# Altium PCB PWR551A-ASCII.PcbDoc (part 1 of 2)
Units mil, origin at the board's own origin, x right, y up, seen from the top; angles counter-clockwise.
Board outline 7100 x 3800 mil, 2 copper layers (Top Layer, Bottom Layer), stack 62 mil thick; 141 components, 57 nets, 323 pads, 168 vias.
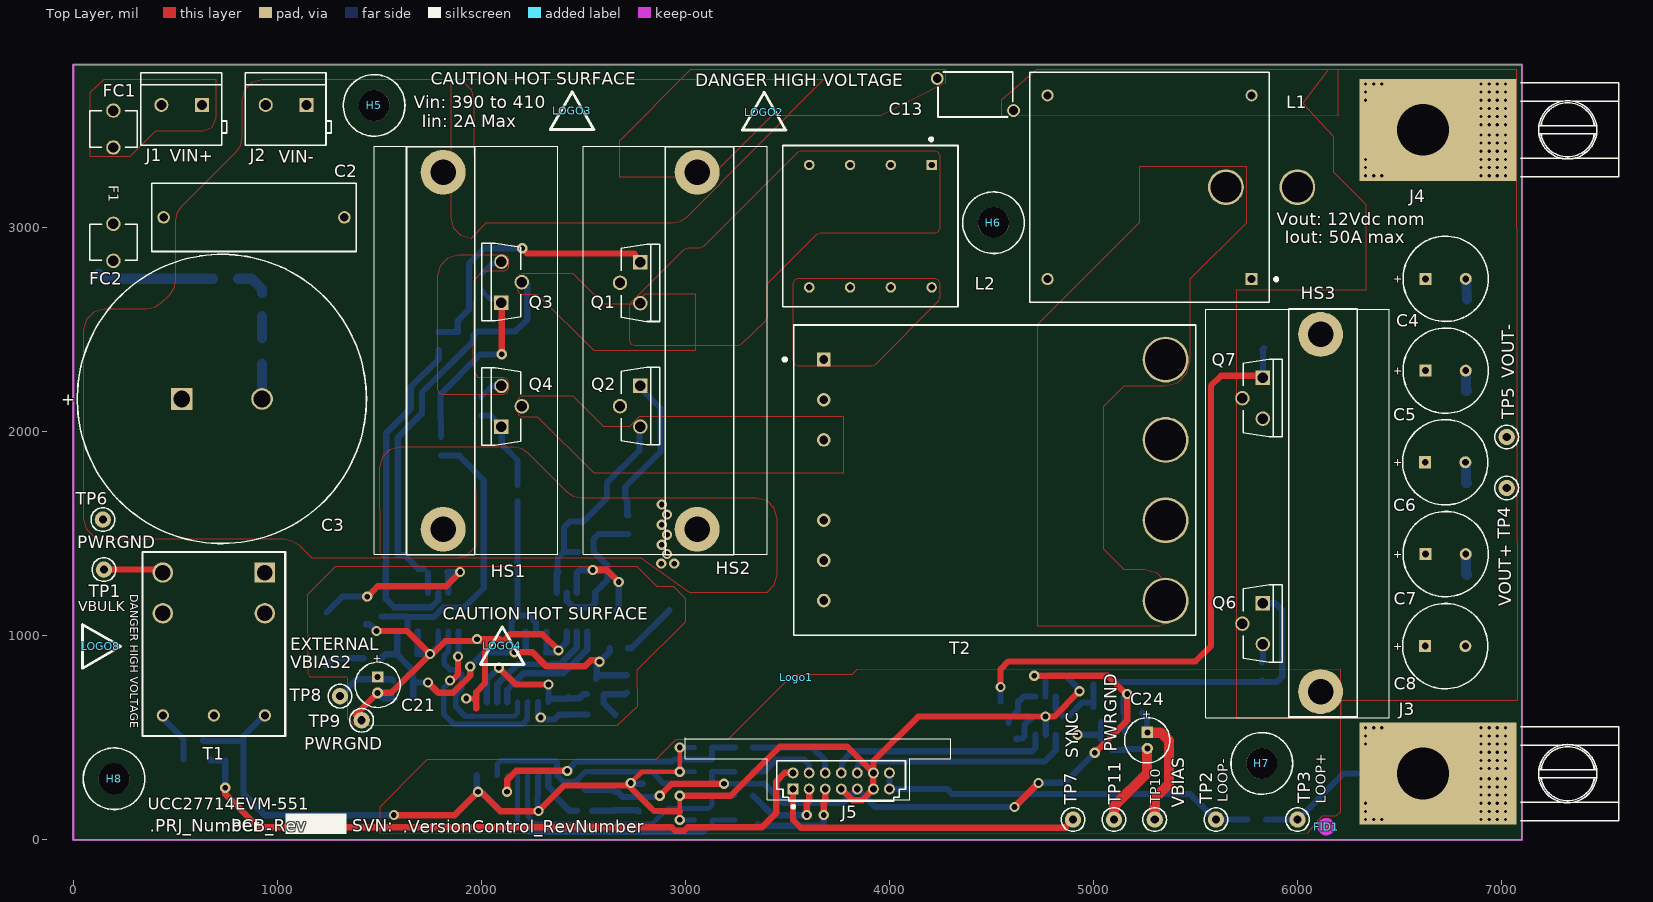
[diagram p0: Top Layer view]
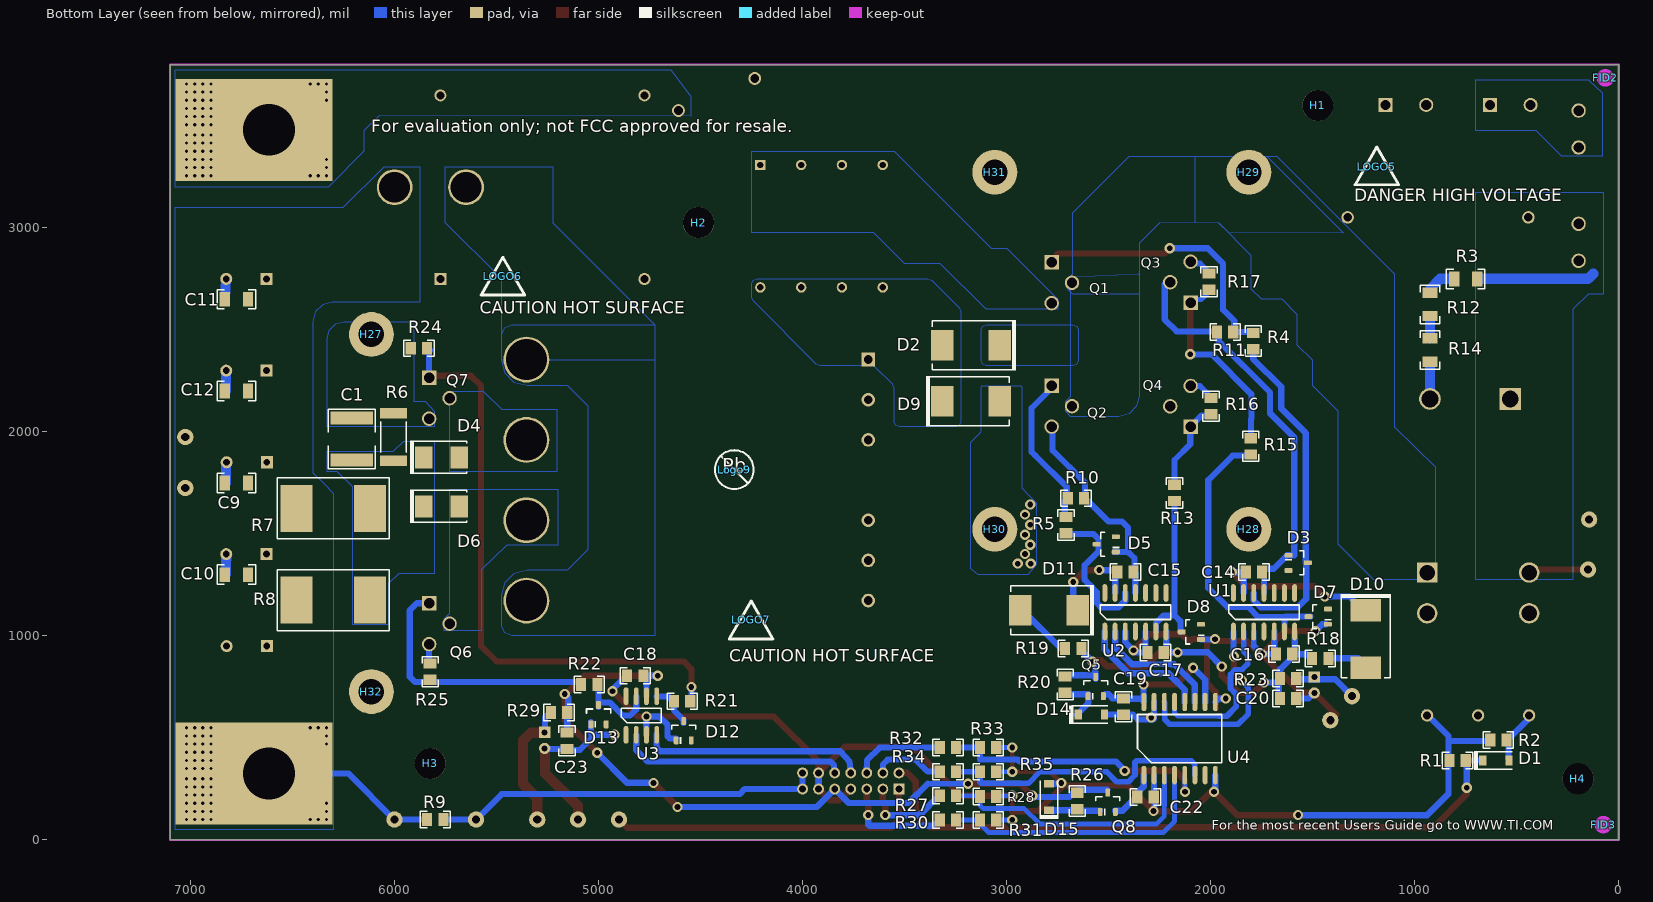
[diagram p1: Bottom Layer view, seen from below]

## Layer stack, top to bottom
Top Layer: signal copper 1.4
Dielectric: core 59.2, FR-4, Dk 4.8
Bottom Layer: signal copper 1.4

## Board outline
0,0 0,3800 7100,3800 7100,0

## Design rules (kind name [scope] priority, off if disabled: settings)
AcuteAngle [All] p0: scope1count=1 scope1_0_kind=Board scope1_0_value=Board scope2count=1 scope2_0_kind=Board scope2_0_value=Board commentlength=0 minimum=4.50000000000000E+0001
AcuteAngle [All] p1: minimum=4.50000000000000E+0001 checktracksonly=TRUE
AssemblyTestPointUsage [All] p0: scope1count=1 scope1_0_kind=Board scope1_0_value=Board scope2count=1 scope2_0_kind=Board scope2_0_value=Board commentlength=0
AssemblyTestPointUsage [All] p1: valid=2
AssemblyTestpoint [All] p0: scope1count=1 scope1_0_kind=Board scope1_0_value=Board scope2count=1 scope2_0_kind=Board scope2_0_value=Board commentlength=0
Clearance Clearance_ALL [All] p0: scope1count=1 scope1_0_kind=Board scope1_0_value=Board scope2count=1 scope2_0_kind=Board scope2_0_value=Board commentlength=0 gap=12
Clearance Clearance_BoardEdge [All] p0 off: scope1count=1 scope1_0_kind=Board scope1_0_value=Board scope2count=1 scope2_0_kind=Board scope2_0_value=Board commentlength=48 gap=19.68 // Protel DXP Scope 2 Expression Was: IsKeepout
Clearance Clearance_BoardEdge_Poly [All] p0 off: scope1count=1 scope1_0_kind=Board scope1_0_value=Board scope2count=1 scope2_0_kind=Board scope2_0_value=Board commentlength=48 gap=19.68 // Protel DXP Scope 2 Expression Was: IsKeepOut
Clearance Clearance_BoardEdge_MountingHoles [All] p0 off: scope1count=1 scope1_0_kind=Board scope1_0_value=Board scope2count=1 scope2_0_kind=Board scope2_0_value=Board commentlength=48 gap=12 // Protel DXP Scope 2 Expression Was: IsKeepOut
Clearance Clearance_Poly [All] p0 off: scope1count=1 scope1_0_kind=Board scope1_0_value=Board scope2count=1 scope2_0_kind=Board scope2_0_value=Board commentlength=48 gap=12 // Protel DXP Scope 1 Expression Was: InPolygon
Clearance ClearanceSW [All] p0 off: scope1count=1 scope1_0_kind=NetClass scope1_0_value=SW scope2count=1 scope2_0_kind=Board scope2_0_value=Board commentlength=75 gap=39.37 // Protel DXP Scope 2 Expression Was: InNetClass('HV') OR InNetClass('LV')
Clearance ClearanceHV [All] p0: scope1count=1 scope1_0_kind=NetClass scope1_0_value=HV scope2count=1 scope2_0_kind=NetClass scope2_0_value="All Nets" commentlength=0 gap=39.37
Clearance Clearance-PRI-SEC [All] p0 off: scope1count=1 scope1_0_kind=NetClass scope1_0_value=SEC scope2count=1 scope2_0_kind=Board scope2_0_value=Board commentlength=95 gap=314.96 // Protel DXP Scope 2 Expression Was: InNetClass('HV') OR InNetClass('SW') OR InNetClass('LV')
Clearance Clearance-PRI-SEC [InNetClass('SEC') vs InNetClass('HV') OR InNetClass('SW') OR InNetClass('LV')] p1: gap=314.96
Clearance ClearanceHV [InNetClass('HV') vs InNetClass('All Nets')] p2: gap=39.37
Clearance ClearanceSW [InNetClass('SW') vs InNetClass('HV') OR InNetClass('LV')] p3: gap=39.37
Clearance Clearance_Poly [InPolygon] p4: gap=12
Clearance Clearance_BoardEdge_MountingHoles [OnCopper and InComponentClass('Mounting Holes') vs IsKeepOut] p5: gap=12
Clearance Clearance_BoardEdge_Poly [OnCopper and InPoly vs IsKeepOut] p6: gap=19.68
Clearance Clearance_BoardEdge [OnCopper and Not InComponentClass('Logo') and not InComponentClass('FiducialMark') and not InRegion(1000,500,4000,800) and Not IsKeepout vs IsKeepout] p7: gap=19.68
Clearance Clearance_ALL [All] p8: gap=12
ComponentClearance [All] p0: scope1count=1 scope1_0_kind=Board scope1_0_value=Board scope2count=1 scope2_0_kind=Board scope2_0_value=Board commentlength=0 gap=0 collisioncheckmode=3
ComponentClearance ComponentClearance_THtoTH [All] p0 off: scope1count=1 scope1_0_kind=Board scope1_0_value=Board scope2count=1 scope2_0_kind=Board scope2_0_value=Board commentlength=54 gap=7.87 collisioncheckmode=3 // Protel DXP Scope 2 Expression Was: IsThruComponent
ComponentClearance ComponentClearance_THtoSMT [All] p0 off: scope1count=1 scope1_0_kind=Board scope1_0_value=Board scope2count=1 scope2_0_kind=Board scope2_0_value=Board commentlength=53 gap=7.87 collisioncheckmode=3 // Protel DXP Scope 2 Expression Was: IsSMTComponent
ComponentClearance ComponentClearance_SmallPassives [All] p0 off: scope1count=1 scope1_0_kind=Board scope1_0_value=Board scope2count=1 scope2_0_kind=Board scope2_0_value=Board commentlength=508 gap=7.87 collisioncheckmode=3 // Protel DXP Scope 2 Expression Was: HasFootprint('0201*') or HasFootprint('0402*') or HasFootprint('0508') or HasFootprint('0603*') or HasFootprint('0612') or HasFootprint('0805*') or HasFootprint('0815*') or HasFootprint('0830*') or HasFootprint('1206*') or HasFootprint('1210*') or HasFootprint('1808*') or HasFootprint('1812*') or HasFootprint('1825*') or HasFootprint('2010*') or HasFootprint('2220*') or HasFootprint('2225*') or HasFootprint('2512*') or HasFootprint('2728*') or HasFootprint('3518*')
ComponentClearance ComponentClearance_MountingHoles [All] p0: scope1count=1 scope1_0_kind=ComponentClass scope1_0_value="Mounting Holes" scope2count=1 scope2_0_kind=Board scope2_0_value=Board commentlength=0 gap=19.68 collisioncheckmode=3
ComponentClearance ComponentClearance_ScrewToNut [All] p0 off: scope1count=1 scope1_0_kind=Board scope1_0_value=Board scope2count=1 scope2_0_kind=Board scope2_0_value=Board commentlength=71 gap=0 collisioncheckmode=3 // Protel DXP Scope 2 Expression Was: (HasFootprint('Keystone_1902C'))
ComponentClearance ComponentClearance_Logo [All] p0: scope1count=1 scope1_0_kind=ComponentClass scope1_0_value=Logo scope2count=1 scope2_0_kind=Board scope2_0_value=Board commentlength=0 gap=3.94 collisioncheckmode=3
ComponentClearance ComponentClearance_Logo [InComponentClass(Logo)] p1: gap=3.94 collisioncheckmode=3 verticalgap=27.56 showdistances=FALSE
ComponentClearance ComponentClearance_ScrewToNut [(HasFootprint('NY PMS 440 0025 PH')) vs (HasFootprint('Keystone_1902C'))] p2: gap=0 collisioncheckmode=3 verticalgap=0 showdistances=FALSE
ComponentClearance ComponentClearance_MountingHoles [InComponentClass('Mounting Holes')] p3: gap=19.68 collisioncheckmode=3 verticalgap=27.56 showdistances=FALSE
ComponentClearance ComponentClearance_SmallPassives [HasFootprint('0201*') or HasFootprint('0402*') or HasFootprint('0508') or HasFootprint('0603*') or HasFootprint('0612') or HasFootprint('0805*') or HasFootprint('0815*') or HasFootprint('0830*') or HasFootprint('1206*') or HasFootprint('1210*') or HasFootprint('1808*') or HasFootprint('1812*') or HasFootprint('1825*') or HasFootprint('2010*') or HasFootprint('2220*') or HasFootprint('2225*') or HasFootprint('2512*') or HasFootprint('2728*') or HasFootprint('3518*') vs HasFootprint('0201*') or HasFootprint('0402*') or HasFootprint('0508') or HasFootprint('0603*') or HasFootprint('0612') or HasFootprint('0805*') or HasFootprint('0815*') or HasFootprint('0830*') or HasFootprint('1206*') or HasFootprint('1210*') or HasFootprint('1808*') or HasFootprint('1812*') or HasFootprint('1825*') or HasFootprint('2010*') or HasFootprint('2220*') or HasFootprint('2225*') or HasFootprint('2512*') or HasFootprint('2728*') or HasFootprint('3518*')] p4: gap=7.87 collisioncheckmode=3 verticalgap=10 showdistances=FALSE
ComponentClearance ComponentClearance_THtoSMT [IsThruComponent vs IsSMTComponent] p5 off: gap=7.87 collisioncheckmode=3 verticalgap=27.56 showdistances=FALSE
ComponentClearance ComponentClearance_THtoTH [IsThruComponent vs IsThruComponent] p6 off: gap=7.87 collisioncheckmode=3 verticalgap=27.56 showdistances=FALSE
ComponentClearance [All] p7: gap=0 collisioncheckmode=3 verticalgap=0 showdistances=FALSE
DiffPairsRouting [All] p0: scope1count=1 scope1_0_kind=Board scope1_0_value=Board scope2count=1 scope2_0_kind=Board scope2_0_value=Board commentlength=0
DiffPairsRouting [All] p1: maxlimit=100 minlimit=10 mostfreqgap=10 maxuncoupledlength=1000
FabricationTestPointUsage TestPointUsage [All] p0: scope1count=1 scope1_0_kind=Board scope1_0_value=Board scope2count=1 scope2_0_kind=Board scope2_0_value=Board commentlength=0 valid=2 allowmultiple=FALSE
FabricationTestPointUsage TestPointUsage [All] p1: valid=2 allowmultiple=FALSE
FabricationTestpoint Testpoint [All] p0: scope1count=1 scope1_0_kind=Board scope1_0_value=Board scope2count=1 scope2_0_kind=Board scope2_0_value=Board commentlength=0 side=3 testpointundercomponent=TRUE minsize=40 maxsize=100 preferedsize=60 minholesize=0 maxholesize=40 preferedholesize=32 testpointgrid=1
FabricationTestpoint Testpoint [All] p1: side=3 testpointundercomponent=TRUE minsize=40 maxsize=100 preferedsize=60 minholesize=0 maxholesize=40 preferedholesize=32 testpointgrid=1 allowsidetop=TRUE allowsidebottom=TRUE usegrid=TRUE gridtolerance=0.01
FanoutControl Fanout_LCC [All] p0 off: scope1count=1 scope1_0_kind=Board scope1_0_value=Board scope2count=1 scope2_0_kind=Board scope2_0_value=Board commentlength=69 // Protel DXP Scope 1 Expression Was: IsLCC   Fanout_LCC (Default Rule)
FanoutControl Fanout_BGA [All] p0 off: scope1count=1 scope1_0_kind=Board scope1_0_value=Board scope2count=1 scope2_0_kind=Board scope2_0_value=Board commentlength=69 // Protel DXP Scope 1 Expression Was: IsBGA   Fanout_BGA (Default Rule)
FanoutControl Fanout_SOIC [All] p0 off: scope1count=1 scope1_0_kind=Board scope1_0_value=Board scope2count=1 scope2_0_kind=Board scope2_0_value=Board commentlength=71 // Protel DXP Scope 1 Expression Was: IsSOIC   Fanout_SOIC (Default Rule)
FanoutControl Fanout_Default [All] p0: scope1count=1 scope1_0_kind=Board scope1_0_value=Board scope2count=1 scope2_0_kind=Board scope2_0_value=Board commentlength=30 // Fanout_Default (Default Rule)
FanoutControl Fanout_Small [All] p0 off: scope1count=1 scope1_0_kind=Board scope1_0_value=Board scope2count=1 scope2_0_kind=Board scope2_0_value=Board commentlength=84 // Protel DXP Scope 1 Expression Was: (CompPinCount < 5)   Fanout_Small (Default Rule)
FanoutControl Fanout_LCC [IsLCC] p1: bgadir=Out bgaviamode=Centered fanoutstyle=Auto fanoutdirection=Alternating viagrid=1 // Fanout_LCC (Default Rule)
FanoutControl Fanout_BGA [IsBGA] p2: bgadir=Out bgaviamode=Centered fanoutstyle=Auto fanoutdirection=Alternating viagrid=1 // Fanout_BGA (Default Rule)
FanoutControl Fanout_Default [All] p4: bgadir=Out bgaviamode=Centered fanoutstyle=Auto fanoutdirection=Alternating viagrid=1 // Fanout_Default (Default Rule)
FanoutControl Fanout_Small [(CompPinCount < 5)] p5: bgadir=Out bgaviamode=Centered fanoutstyle=Auto fanoutdirection=OutThenIn viagrid=1 // Fanout_Small (Default Rule)
Height Height_top [All] p0 off: scope1count=1 scope1_0_kind=Board scope1_0_value=Board scope2count=1 scope2_0_kind=Board scope2_0_value=Board commentlength=61 // Protel DXP Scope 1 Expression Was: (OnLayer('Top Layer'))
Height "Height Bottom" [All] p0 off: scope1count=1 scope1_0_kind=Board scope1_0_value=Board scope2count=1 scope2_0_kind=Board scope2_0_value=Board commentlength=64 // Protel DXP Scope 1 Expression Was: (OnLayer('Bottom Layer'))
Height "Height Bottom" [(OnLayer('Bottom Layer'))] p1: minheight=0 maxheight=1000 prefheight=500
Height Height_top [(OnLayer('Top Layer'))] p2: minheight=0 maxheight=1750 prefheight=1750
HoleSize [All] p0: scope1count=1 scope1_0_kind=Board scope1_0_value=Board scope2count=1 scope2_0_kind=Board scope2_0_value=Board commentlength=0 absolutevalues=TRUE maxlimit=275.59 minlimit=8 maxpercent=80.000 minpercent=20.000
HoleSize [All] p1: absolutevalues=TRUE maxlimit=275.59 minlimit=8 maxpercent=80.000 minpercent=20.000
HoleToHoleClearance [All] p0: scope1count=1 scope1_0_kind=Board scope1_0_value=Board scope2count=1 scope2_0_kind=Board scope2_0_value=Board commentlength=0
LayerPairs [All] p0: scope1count=1 scope1_0_kind=Board scope1_0_value=Board scope2count=1 scope2_0_kind=Board scope2_0_value=Board commentlength=0 enforce=TRUE
MinimumAnnularRing [All] p0: scope1count=1 scope1_0_kind=Board scope1_0_value=Board scope2count=1 scope2_0_kind=Board scope2_0_value=Board commentlength=0 minimumring=8
MinimumAnnularRing [All] p1: minimumring=8
MinimumSolderMaskSliver [All] p0: scope1count=1 scope1_0_kind=Board scope1_0_value=Board scope2count=1 scope2_0_kind=Board scope2_0_value=Board commentlength=0
MinimumSolderMaskSliver MinimumSolderMaskSliver_Logo [All] p0: scope1count=1 scope1_0_kind=ComponentClass scope1_0_value=Logo scope2count=1 scope2_0_kind=ComponentClass scope2_0_value=Logo commentlength=0
MinimumSolderMaskSliver MinimumSolderMaskSliver_Logo [InComponentClass('Logo') vs InComponentClass('Logo')] p1: minsoldermaskwidth=0.7
MinimumSolderMaskSliver [All] p2: minsoldermaskwidth=4
NetAntennae [All] p0: scope1count=1 scope1_0_kind=Board scope1_0_value=Board scope2count=1 scope2_0_kind=Board scope2_0_value=Board commentlength=0
PasteMaskExpansion [All] p0: scope1count=1 scope1_0_kind=Board scope1_0_value=Board scope2count=1 scope2_0_kind=Board scope2_0_value=Board commentlength=0 expansion=0
PlaneClearance [All] p0: scope1count=1 scope1_0_kind=Board scope1_0_value=Board scope2count=1 scope2_0_kind=Board scope2_0_value=Board commentlength=0 clearance=20
PlaneConnect [All] p0: scope1count=1 scope1_0_kind=Board scope1_0_value=Board scope2count=1 scope2_0_kind=Board scope2_0_value=Board commentlength=0 planeconnectstyle=Relief reliefexpansion=10 reliefentries=4 reliefconductorwidth=10 reliefairgap=10
PlaneConnect [All] p1: planeconnectstyle=Relief reliefexpansion=10 reliefentries=4 reliefconductorwidth=10 reliefairgap=10
PolygonConnect PolygonConnect_23 [All] p0 off: scope1count=1 scope1_0_kind=Board scope1_0_value=Board scope2count=1 scope2_0_kind=Board scope2_0_value=Board commentlength=80 connectstyle=Direct reliefconductorwidth=10 reliefentries=4 polygonreliefangle="90 Angle" // Protel DXP Scope 2 Expression Was: IsNamedPolygon('Top Layer, Top-PWRGND 4')
PolygonConnect PolygonConnect_22 [All] p0 off: scope1count=1 scope1_0_kind=Board scope1_0_value=Board scope2count=1 scope2_0_kind=Board scope2_0_value=Board commentlength=80 connectstyle=Direct reliefconductorwidth=10 reliefentries=4 polygonreliefangle="90 Angle" // Protel DXP Scope 2 Expression Was: IsNamedPolygon('Top Layer, Top-PWRGND 4')
PolygonConnect PolygonConnect_21 [All] p0 off: scope1count=1 scope1_0_kind=Board scope1_0_value=Board scope2count=1 scope2_0_kind=Board scope2_0_value=Board commentlength=80 connectstyle=Direct reliefconductorwidth=10 reliefentries=4 polygonreliefangle="90 Angle" // Protel DXP Scope 2 Expression Was: IsNamedPolygon('Top Layer, Top-PWRGND 2')
PolygonConnect PolygonConnect_20 [All] p0 off: scope1count=1 scope1_0_kind=Board scope1_0_value=Board scope2count=1 scope2_0_kind=Board scope2_0_value=Board commentlength=80 connectstyle=Direct reliefconductorwidth=10 reliefentries=4 polygonreliefangle="90 Angle" // Protel DXP Scope 2 Expression Was: IsNamedPolygon('Top Layer, Top-PWRGND 3')
PolygonConnect PolygonConnect_19 [All] p0 off: scope1count=1 scope1_0_kind=Board scope1_0_value=Board scope2count=1 scope2_0_kind=Board scope2_0_value=Board commentlength=80 connectstyle=Direct reliefconductorwidth=10 reliefentries=4 polygonreliefangle="90 Angle" // Protel DXP Scope 2 Expression Was: IsNamedPolygon('Top Layer, Top-PWRGND 4')
PolygonConnect PolygonConnect_18 [All] p0 off: scope1count=1 scope1_0_kind=Board scope1_0_value=Board scope2count=1 scope2_0_kind=Board scope2_0_value=Board commentlength=75 connectstyle=Direct reliefconductorwidth=10 reliefentries=4 polygonreliefangle="90 Angle" // Protel DXP Scope 2 Expression Was: IsNamedPolygon('Top Layer, Top-GND')
PolygonConnect PolygonConnect_17 [All] p0 off: scope1count=1 scope1_0_kind=Board scope1_0_value=Board scope2count=1 scope2_0_kind=Board scope2_0_value=Board commentlength=77 connectstyle=Direct reliefconductorwidth=10 reliefentries=4 polygonreliefangle="90 Angle" // Protel DXP Scope 2 Expression Was: IsNamedPolygon('Top Layer, Top-GND 1')
PolygonConnect PolygonConnect_16 [All] p0 off: scope1count=1 scope1_0_kind=Board scope1_0_value=Board scope2count=1 scope2_0_kind=Board scope2_0_value=Board commentlength=77 connectstyle=Direct reliefconductorwidth=10 reliefentries=4 polygonreliefangle="90 Angle" // Protel DXP Scope 2 Expression Was: IsNamedPolygon('Top Layer, Top-GND 2')
PolygonConnect PolygonConnect_15 [All] p0 off: scope1count=1 scope1_0_kind=Board scope1_0_value=Board scope2count=1 scope2_0_kind=Board scope2_0_value=Board commentlength=80 connectstyle=Direct reliefconductorwidth=10 reliefentries=4 polygonreliefangle="90 Angle" // Protel DXP Scope 2 Expression Was: IsNamedPolygon('Top Layer, Top-NET00002')
PolygonConnect PolygonConnect_14 [All] p0 off: scope1count=1 scope1_0_kind=Board scope1_0_value=Board scope2count=1 scope2_0_kind=Board scope2_0_value=Board commentlength=80 connectstyle=Direct reliefconductorwidth=10 reliefentries=4 polygonreliefangle="90 Angle" // Protel DXP Scope 2 Expression Was: IsNamedPolygon('Top Layer, Top-NET00003')
PolygonConnect PolygonConnect_13 [All] p0 off: scope1count=1 scope1_0_kind=Board scope1_0_value=Board scope2count=1 scope2_0_kind=Board scope2_0_value=Board commentlength=80 connectstyle=Direct reliefconductorwidth=10 reliefentries=4 polygonreliefangle="90 Angle" // Protel DXP Scope 2 Expression Was: IsNamedPolygon('Top Layer, Top-NET00003')
PolygonConnect PolygonConnect_12 [All] p0 off: scope1count=1 scope1_0_kind=Board scope1_0_value=Board scope2count=1 scope2_0_kind=Board scope2_0_value=Board commentlength=80 connectstyle=Direct reliefconductorwidth=10 reliefentries=4 polygonreliefangle="90 Angle" // Protel DXP Scope 2 Expression Was: IsNamedPolygon('Top Layer, Top-NET00007')
PolygonConnect PolygonConnect_11 [All] p0 off: scope1count=1 scope1_0_kind=Board scope1_0_value=Board scope2count=1 scope2_0_kind=Board scope2_0_value=Board commentlength=80 connectstyle=Direct reliefconductorwidth=10 reliefentries=4 polygonreliefangle="90 Angle" // Protel DXP Scope 2 Expression Was: IsNamedPolygon('Top Layer, Top-NET00016')
PolygonConnect PolygonConnect_10 [All] p0 off: scope1count=1 scope1_0_kind=Board scope1_0_value=Board scope2count=1 scope2_0_kind=Board scope2_0_value=Board commentlength=80 connectstyle=Direct reliefconductorwidth=10 reliefentries=4 polygonreliefangle="90 Angle" // Protel DXP Scope 2 Expression Was: IsNamedPolygon('Top Layer, Top-NET00025')
PolygonConnect PolygonConnect_9 [All] p0 off: scope1count=1 scope1_0_kind=Board scope1_0_value=Board scope2count=1 scope2_0_kind=Board scope2_0_value=Board commentlength=82 connectstyle=Direct reliefconductorwidth=10 reliefentries=4 polygonreliefangle="90 Angle" // Protel DXP Scope 2 Expression Was: IsNamedPolygon('Top Layer, Top-NET00025 1')
PolygonConnect PolygonConnect_8 [All] p0 off: scope1count=1 scope1_0_kind=Board scope1_0_value=Board scope2count=1 scope2_0_kind=Board scope2_0_value=Board commentlength=78 connectstyle=Direct reliefconductorwidth=10 reliefentries=4 polygonreliefangle="90 Angle" // Protel DXP Scope 2 Expression Was: IsNamedPolygon('Top Layer, Top-No Net')
PolygonConnect PolygonConnect_7 [All] p0 off: scope1count=1 scope1_0_kind=Board scope1_0_value=Board scope2count=1 scope2_0_kind=Board scope2_0_value=Board commentlength=78 connectstyle=Direct reliefconductorwidth=10 reliefentries=4 polygonreliefangle="90 Angle" // Protel DXP Scope 2 Expression Was: IsNamedPolygon('Top Layer, Top-PWRGND')
PolygonConnect PolygonConnect_6 [All] p0 off: scope1count=1 scope1_0_kind=Board scope1_0_value=Board scope2count=1 scope2_0_kind=Board scope2_0_value=Board commentlength=80 connectstyle=Direct reliefconductorwidth=10 reliefentries=4 polygonreliefangle="90 Angle" // Protel DXP Scope 2 Expression Was: IsNamedPolygon('Top Layer, Top-PWRGND 1')
PolygonConnect PolygonConnect_5 [All] p0 off: scope1count=1 scope1_0_kind=Board scope1_0_value=Board scope2count=1 scope2_0_kind=Board scope2_0_value=Board commentlength=80 connectstyle=Direct reliefconductorwidth=10 reliefentries=4 polygonreliefangle="90 Angle" // Protel DXP Scope 2 Expression Was: IsNamedPolygon('Top Layer, Top-PWRGND 2')
PolygonConnect PolygonConnect_4 [All] p0 off: scope1count=1 scope1_0_kind=Board scope1_0_value=Board scope2count=1 scope2_0_kind=Board scope2_0_value=Board commentlength=80 connectstyle=Direct reliefconductorwidth=10 reliefentries=4 polygonreliefangle="90 Angle" // Protel DXP Scope 2 Expression Was: IsNamedPolygon('Top Layer, Top-PWRGND 3')
PolygonConnect PolygonConnect_3 [All] p0 off: scope1count=1 scope1_0_kind=Board scope1_0_value=Board scope2count=1 scope2_0_kind=Board scope2_0_value=Board commentlength=80 connectstyle=Direct reliefconductorwidth=10 reliefentries=4 polygonreliefangle="90 Angle" // Protel DXP Scope 2 Expression Was: IsNamedPolygon('Top Layer, Top-PWRGND 4')
PolygonConnect PolygonConnect_2 [All] p0 off: scope1count=1 scope1_0_kind=Board scope1_0_value=Board scope2count=1 scope2_0_kind=Board scope2_0_value=Board commentlength=126 connectstyle=Direct reliefconductorwidth=10 reliefentries=4 polygonreliefangle="90 Angle" // Protel DXP Scope 2 Expression Was: IsNamedPolygon('Top Layer, Top-PWRGND 3') Or  IsNamedPolygon('Top Layer, Top-PWRGND 4')
PolygonConnect PolygonConnect_1 [All] p0 off: scope1count=1 scope1_0_kind=Board scope1_0_value=Board scope2count=1 scope2_0_kind=Board scope2_0_value=Board commentlength=1642 connectstyle=Direct reliefconductorwidth=10 reliefentries=4 polygonreliefangle="90 Angle" // Protel DXP Scope 2 Expression Was: IsNamedPolygon('Top Layer, Top-PWRGND 2') Or  IsNamedPolygon('Bottom Layer, Bottom-GND') Or  IsNamedPolygon('Bottom Layer, Bottom-NET00038') Or  IsNamedPolygon('Bottom Layer, Bottom-NET00006') Or  IsNamedPolygon('Bottom Layer, Bottom-NET00003') Or  IsNamedPolygon('Bottom Layer, Bottom-NET00004 2') Or  IsNamedPolygon('Bottom Layer, Bottom-NET00020') Or  IsNamedPolygon('Bottom Layer, Bottom-GND 2') Or  IsNamedPolygon('Bottom Layer, Bottom-NET00004') Or  IsNamedPolygon('Bottom Layer, Bottom-PWRGND') Or  IsNamedPolygon('Bottom Layer, Bottom-NET00002 1') Or  IsNamedPolygon('Bottom Layer, Bottom-NET00013') Or  IsNamedPolygon('Bottom Layer, Bottom-NET00012') Or  IsNamedPolygon('Bottom Layer, Bottom-NET00004 3') Or  IsNamedPolygon('Bottom Layer, Bottom-NET00004 1') Or  IsNamedPolygon('Bottom Layer, Bottom-NET00016') Or  IsNamedPolygon('Bottom Layer, Bottom-GND 1') Or  IsNamedPolygon('Bottom Layer, Bottom-NET00025') Or  IsNamedPolygon('Bottom Layer, Bottom-NET00002') Or  IsNamedPolygon('Top Layer, Top-No Net') Or  IsNamedPolygon('Top Layer, Top-NET00016') Or  IsNamedPolygon('Top Layer, Top-NET00025 1') Or  IsNamedPolygon('Top Layer, Top-GND 2') Or  IsNamedPolygon('Top Layer, Top-PWRGND 3') Or  IsNamedPolygon('Top Layer, Top-PWRGND 4') Or  IsNamedPolygon('Top Layer, Top-NET00002') Or  IsNamedPolygon('Top Layer, Top-NET00007') Or  IsNamedPolygon('Top Layer, Top-GND 1') Or  IsNamedPolygon('Top Layer, Top-PWRGND 1') Or  IsNamedPolygon('Top Layer, Top-GND') Or  IsNamedPolygon('Top Layer, Top-NET00025') Or  IsNamedPolygon('Top Layer, Top-NET00003') Or  IsNamedPolygon('Top Layer, Top-PWRGND')
PolygonConnect [All] p0: scope1count=1 scope1_0_kind=Board scope1_0_value=Board scope2count=1 scope2_0_kind=Board scope2_0_value=Board commentlength=0 connectstyle=Relief reliefconductorwidth=10 reliefentries=4 polygonreliefangle="90 Angle"
PolygonConnect PolygonConnect_23 [All vs IsNamedPolygon('Top Layer, Top-PWRGND 4')] p1: connectstyle=Direct reliefconductorwidth=10 reliefentries=4 polygonreliefangle="90 Angle" airgapwidth=10
PolygonConnect PolygonConnect_22 [All vs IsNamedPolygon('Top Layer, Top-PWRGND 4')] p2: connectstyle=Direct reliefconductorwidth=10 reliefentries=4 polygonreliefangle="90 Angle" airgapwidth=10
PolygonConnect PolygonConnect_21 [All vs IsNamedPolygon('Top Layer, Top-PWRGND 2')] p3: connectstyle=Direct reliefconductorwidth=10 reliefentries=4 polygonreliefangle="90 Angle" airgapwidth=10
PolygonConnect PolygonConnect_20 [All vs IsNamedPolygon('Top Layer, Top-PWRGND 3')] p4: connectstyle=Direct reliefconductorwidth=10 reliefentries=4 polygonreliefangle="90 Angle" airgapwidth=10
PolygonConnect PolygonConnect_19 [All vs IsNamedPolygon('Top Layer, Top-PWRGND 4')] p5: connectstyle=Direct reliefconductorwidth=10 reliefentries=4 polygonreliefangle="90 Angle" airgapwidth=10
PolygonConnect PolygonConnect_18 [All vs IsNamedPolygon('Top Layer, Top-GND')] p6: connectstyle=Direct reliefconductorwidth=10 reliefentries=4 polygonreliefangle="90 Angle" airgapwidth=10
PolygonConnect PolygonConnect_17 [All vs IsNamedPolygon('Top Layer, Top-GND 1')] p7: connectstyle=Direct reliefconductorwidth=10 reliefentries=4 polygonreliefangle="90 Angle" airgapwidth=10
PolygonConnect PolygonConnect_16 [All vs IsNamedPolygon('Top Layer, Top-GND 2')] p8: connectstyle=Direct reliefconductorwidth=10 reliefentries=4 polygonreliefangle="90 Angle" airgapwidth=10
PolygonConnect PolygonConnect_15 [All vs IsNamedPolygon('Top Layer, Top-NET00002')] p9: connectstyle=Direct reliefconductorwidth=10 reliefentries=4 polygonreliefangle="90 Angle" airgapwidth=10
PolygonConnect PolygonConnect_14 [All vs IsNamedPolygon('Top Layer, Top-NET00003')] p10: connectstyle=Direct reliefconductorwidth=10 reliefentries=4 polygonreliefangle="90 Angle" airgapwidth=10
PolygonConnect PolygonConnect_13 [All vs IsNamedPolygon('Top Layer, Top-NET00003')] p11: connectstyle=Direct reliefconductorwidth=10 reliefentries=4 polygonreliefangle="90 Angle" airgapwidth=10
PolygonConnect PolygonConnect_12 [All vs IsNamedPolygon('Top Layer, Top-NET00007')] p12: connectstyle=Direct reliefconductorwidth=10 reliefentries=4 polygonreliefangle="90 Angle" airgapwidth=10
PolygonConnect PolygonConnect_11 [All vs IsNamedPolygon('Top Layer, Top-NET00016')] p13: connectstyle=Direct reliefconductorwidth=10 reliefentries=4 polygonreliefangle="90 Angle" airgapwidth=10
PolygonConnect PolygonConnect_10 [All vs IsNamedPolygon('Top Layer, Top-NET00025')] p14: connectstyle=Direct reliefconductorwidth=10 reliefentries=4 polygonreliefangle="90 Angle" airgapwidth=10
PolygonConnect PolygonConnect_9 [All vs IsNamedPolygon('Top Layer, Top-NET00025 1')] p15: connectstyle=Direct reliefconductorwidth=10 reliefentries=4 polygonreliefangle="90 Angle" airgapwidth=10
PolygonConnect PolygonConnect_8 [All vs IsNamedPolygon('Top Layer, Top-No Net')] p16: connectstyle=Direct reliefconductorwidth=10 reliefentries=4 polygonreliefangle="90 Angle" airgapwidth=10
PolygonConnect PolygonConnect_7 [All vs IsNamedPolygon('Top Layer, Top-PWRGND')] p17: connectstyle=Direct reliefconductorwidth=10 reliefentries=4 polygonreliefangle="90 Angle" airgapwidth=10
PolygonConnect PolygonConnect_6 [All vs IsNamedPolygon('Top Layer, Top-PWRGND 1')] p18: connectstyle=Direct reliefconductorwidth=10 reliefentries=4 polygonreliefangle="90 Angle" airgapwidth=10
PolygonConnect PolygonConnect_5 [All vs IsNamedPolygon('Top Layer, Top-PWRGND 2')] p19: connectstyle=Direct reliefconductorwidth=10 reliefentries=4 polygonreliefangle="90 Angle" airgapwidth=10
PolygonConnect PolygonConnect_4 [All vs IsNamedPolygon('Top Layer, Top-PWRGND 3')] p20: connectstyle=Direct reliefconductorwidth=10 reliefentries=4 polygonreliefangle="90 Angle" airgapwidth=10
PolygonConnect PolygonConnect_3 [All vs IsNamedPolygon('Top Layer, Top-PWRGND 4')] p21: connectstyle=Direct reliefconductorwidth=10 reliefentries=4 polygonreliefangle="90 Angle" airgapwidth=10
PolygonConnect PolygonConnect_2 [All vs IsNamedPolygon('Top Layer, Top-PWRGND 3') Or  IsNamedPolygon('Top Layer, Top-PWRGND 4')] p22: connectstyle=Direct reliefconductorwidth=10 reliefentries=4 polygonreliefangle="90 Angle" airgapwidth=10
PolygonConnect PolygonConnect_1 [All vs IsNamedPolygon('Top Layer, Top-PWRGND 2') Or  IsNamedPolygon('Bottom Layer, Bottom-GND') Or  IsNamedPolygon('Bottom Layer, Bottom-NET00038') Or  IsNamedPolygon('Bottom Layer, Bottom-NET00006') Or  IsNamedPolygon('Bottom Layer, Bottom-NET00003') Or  IsNamedPolygon('Bottom Layer, Bottom-NET00004 2') Or  IsNamedPolygon('Bottom Layer, Bottom-NET00020') Or  IsNamedPolygon('Bottom Layer, Bottom-GND 2') Or  IsNamedPolygon('Bottom Layer, Bottom-NET00004') Or  IsNamedPolygon('Bottom Layer, Bottom-PWRGND') Or  IsNamedPolygon('Bottom Layer, Bottom-NET00002 1') Or  IsNamedPolygon('Bottom Layer, Bottom-NET00013') Or  IsNamedPolygon('Bottom Layer, Bottom-NET00012') Or  IsNamedPolygon('Bottom Layer, Bottom-NET00004 3') Or  IsNamedPolygon('Bottom Layer, Bottom-NET00004 1') Or  IsNamedPolygon('Bottom Layer, Bottom-NET00016') Or  IsNamedPolygon('Bottom Layer, Bottom-GND 1') Or  IsNamedPolygon('Bottom Layer, Bottom-NET00025') Or  IsNamedPolygon('Bottom Layer, Bottom-NET00002') Or  IsNamedPolygon('Top Layer, Top-No Net') Or  IsNamedPolygon('Top Layer, Top-NET00016') Or  IsNamedPolygon('Top Layer, Top-NET00025 1') Or  IsNamedPolygon('Top Layer, Top-GND 2') Or  IsNamedPolygon('Top Layer, Top-PWRGND 3') Or  IsNamedPolygon('Top Layer, Top-PWRGND 4') Or  IsNamedPolygon('Top Layer, Top-NET00002') Or  IsNamedPolygon('Top Layer, Top-NET00007') Or  IsNamedPolygon('Top Layer, Top-GND 1') Or  IsNamedPolygon('Top Layer, Top-PWRGND 1') Or  IsNamedPolygon('Top Layer, Top-GND') Or  IsNamedPolygon('Top Layer, Top-NET00025') Or  IsNamedPolygon('Top Layer, Top-NET00003') Or  IsNamedPolygon('Top Layer, Top-PWRGND')] p23: connectstyle=Direct reliefconductorwidth=10 reliefentries=4 polygonreliefangle="90 Angle" airgapwidth=10
PolygonConnect [All] p24: connectstyle=Relief reliefconductorwidth=10 reliefentries=4 polygonreliefangle="90 Angle" airgapwidth=10
RoutingCorners [All] p0: scope1count=1 scope1_0_kind=Board scope1_0_value=Board scope2count=1 scope2_0_kind=Board scope2_0_value=Board commentlength=0 cornerstyle=45-Degree minsetback=100 maxsetback=100
RoutingLayers [All] p0: scope1count=1 scope1_0_kind=Board scope1_0_value=Board scope2count=1 scope2_0_kind=Board scope2_0_value=Board commentlength=0 top layer=Automatic bottom layer=Automatic
RoutingPriority [All] p0: scope1count=1 scope1_0_kind=Board scope1_0_value=Board scope2count=1 scope2_0_kind=Board scope2_0_value=Board commentlength=0
RoutingTopology [All] p0: scope1count=1 scope1_0_kind=Board scope1_0_value=Board scope2count=1 scope2_0_kind=Board scope2_0_value=Board commentlength=0 topology=Shortest
RoutingVias [All] p0: scope1count=1 scope1_0_kind=Board scope1_0_value=Board scope2count=1 scope2_0_kind=Board scope2_0_value=Board commentlength=0 holewidth=16 width=34 viastyle="Through Hole" minholewidth=8 minwidth=26 maxholewidth=40 maxwidth=65
RoutingVias [All] p1: holewidth=16 width=34 viastyle="Through Hole" minholewidth=8 minwidth=26 maxholewidth=40 maxwidth=65
SMDToCorner [All] p0: scope1count=1 scope1_0_kind=Board scope1_0_value=Board scope2count=1 scope2_0_kind=Board scope2_0_value=Board commentlength=0 distance=30000
SMDToCorner [All] p1: distance=30000
ShortCircuit [All] p0: scope1count=1 scope1_0_kind=Board scope1_0_value=Board scope2count=1 scope2_0_kind=Board scope2_0_value=Board commentlength=0 allowed=FALSE
SilkToSilkClearance [All] p0 off: scope1count=1 scope1_0_kind=Board scope1_0_value=Board scope2count=1 scope2_0_kind=Board scope2_0_value=Board commentlength=0
SilkToSilkClearance [All] p1 off: silktosilkclearance=4.5
SilkscreenOverComponentPads [All] p0: scope1count=1 scope1_0_kind=Board scope1_0_value=Board scope2count=1 scope2_0_kind=Board scope2_0_value=Board commentlength=0
SilkscreenOverComponentPads [All] p1: minsilkscreentomaskgap=5
SolderMaskExpansion [All] p0: scope1count=1 scope1_0_kind=Board scope1_0_value=Board scope2count=1 scope2_0_kind=Board scope2_0_value=Board commentlength=0 expansion=3
SolderMaskExpansion [All] p1: expansion=3
UnRoutedNet [All] p0: scope1count=1 scope1_0_kind=Board scope1_0_value=Board scope2count=1 scope2_0_kind=Board scope2_0_value=Board commentlength=0
Width [All] p0: scope1count=1 scope1_0_kind=Board scope1_0_value=Board scope2count=1 scope2_0_kind=Board scope2_0_value=Board commentlength=0 maxlimit=100 minlimit=19.68 preferedwidth=31.5
Width [All] p1: maxlimit=100 minlimit=19.68 preferedwidth=31.5 checkconnectedcopper=TRUE
13 further rules are at their usual default settings.

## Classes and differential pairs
component class Screw: H27 H28 H29 H30 H31 H32
net class SW: NetC14_1 NetC15_1
net class HV: NetC2_2 NetD2_1 NetF1_1 NetF1_2 NetFC1_1 NetR3_1 NetR12_1
net class SEC: CS GND NetC1_2 NetC4_1 NetC22_2 NetC24_1 NetD1_2 NetD4_2 NetD6_2 NetD12_3 NetD13_3 NetD15_1 NetL1_13 NetQ6_1 NetQ7_1 NetR27_2 NetR30_2 NetR32_2 NetR34_2 NetU3_1 NetU3_8 NetU4_7 OUTA OUTB OUTC OUTD OUTE OUTF SYNC VBIAS VOUT
component class PWR551A_Sht01: C1 C2 C3 C4 C5 C6 C7 C8 C9 C10 C11 C12 C13 C14 C15 C16 C17 C18 C19 C20 C21 C22 C23 C24 D1 D2 D3 D4 D5 D6 D7 D8 D9 D10 D11 D12 D13 D14 D15 F1 FC1 FC2 HS1 HS2 HS3 J1 J2 J3 J4 J5 L1 L2 Q1 Q2 Q3 Q4 Q5 Q6 Q7 Q8 R1 R2 R3 R4 R5 R6 R7 R8 R9 R10 R11 R12 R13 R14 R15 R16 R17 R18 R19 R20 R21 R22 R23 R24 R25 R26 R27 R28 R29 R30 R31 R32 R33 R34 R35 T1 T2 TP1 TP2 TP3 TP4 TP5 TP6 TP7 TP8 TP9 TP10 TP11 U1 U2 U3 U4
component class PWR551A_Hardware: !PCB FID1 FID2 FID3 H1 H2 H3 H4 H5 H6 H7 H8 H27 H28 H29 H30 H31 H32 Logo1 LOGO2 LOGO3 LOGO4 LOGO5 LOGO6 LOGO7 LOGO8 Logo9 ZZ1 ZZ2 ZZ3 ZZ4
component class Logo: Logo1
component class FiducialMark: FID1 FID2 FID3
component class AssemblyNote: ZZ1 ZZ2 ZZ3 ZZ4

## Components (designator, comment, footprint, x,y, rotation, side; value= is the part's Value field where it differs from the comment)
C1 "C2220C224J1GACTU" 2220 6210,1965 r270 bottom
C2 "ECQ-U2A474ML" CAPRR2250W80L2550T850H1750 885.83,3051.18 r180 top
C3 "EET-HC2W331EA" TS-HC_3500x3500 728.35,2161.42 r0 top
C4 "EKY-160ELL152MJ30S" KY_1000x3000 6726,2750 r0 top
C5 "EKY-160ELL152MJ30S" KY_1000x3000 6726,2300 r0 top
C6 "EKY-160ELL152MJ30S" KY_1000x3000 6724,1851 r0 top
C7 "EKY-160ELL152MJ30S" KY_1000x3000 6726,1401 r0 top
C8 "EKY-160ELL152MJ30S" KY_1000x3000 6724,950 r0 top
C9 "C3216X7R1E105K085AA" 1206 6775,1750 r180 bottom
C10 "C3216X7R1E105K085AA" 1206 6775,1300 r180 bottom
C11 "C3216X7R1E105K085AA" 1206 6775,2650 r180 bottom
C12 "C3216X7R1E105K085AA" 1206 6775,2200 r180 bottom
C13 "440LD10-R" 440L_930x1250 4421.26,3653.54 r180 top
C14 "C2012X7R1H104K" 0805_HV 1787.8,1312.99 r0 bottom
C15 "C2012X7R1H104K" 0805_HV 2417.72,1312.99 r0 bottom
C16 "C2012X7R1E105K" 0805_HV 1640.16,910.87 r180 bottom
C17 "C2012X7R1E105K" 0805_HV 2270.08,919.29 r180 bottom
C18 "C2012X7R1E105K" 0805_HV 4820,805 r180 bottom
C19 "C2012X7R1E105K" 0805_HV 2427.56,653.54 r90 bottom
C20 "C2012X7R1E105K" 0805_HV 1620.47,692.91 r0 bottom
C21 "ECA-1VM220" M_500x1100 1492.13,759.84 r270 top
C22 "C2012X7R1E105K" 0805_HV 2319.29,210.63 r0 bottom
C23 "C2012X7R1E105K" 0805_HV 5153.94,486.22 r90 bottom
C24 "ECA-1VM220" M_500x1100 5263.78,488.19 r270 top
D1 "1N4148W-7-F" SOD-123 602.36,389.76 r180 bottom
D2 "MURS360T3G" SMC 3175,2425 r0 bottom
D3 "BAT54-7-F" SOT-23 1570.87,1358.27 r180 bottom
D4 "ES3BB-13-F" SMB 5770,1875 r180 bottom
D5 "BAT54-7-F" SOT-23 2511.81,1448.82 r0 bottom
D6 "ES3BB-13-F" SMB 5770,1635 r180 bottom
D7 "BAT54-7-F" SOT-23 1472.44,1094.49 r0 bottom
D8 "BAT54-7-F" SOT-23 2094.49,1019.68 r0 bottom
D9 "MURS360T3G" SMC 3175,2150 r180 bottom
D10 "MURS360T3G" SMC 1240.16,984.25 r270 bottom
D11 "MURS360T3G" SMC 2791.73,1125.98 r0 bottom
D12 "BAT54-7-F" SOT-23 4582.68,535.43 r90 bottom
D13 "BAT54-7-F" SOT-23 5000,614.17 r90 bottom
D14 "MMSZ5232B-7-F" SOD-123 2585.04,614.17 r180 bottom
D15 "MMSZ5232B-7-F" SOD-123 2791.73,210.63 r90 bottom
FC1 "01000056Z" Littelfuse_0100-0020_54_56 196.85,3484.25 r90 top
FC2 "01000056Z" Littelfuse_0100-0020_54_56 196.85,2929.13 r270 top
FID1 "Fiducial" Fiducial10-20 6140,65 r0 top
FID2 "Fiducial" Fiducial10-20 65,3735 r180 bottom (schematic designator FID3)
FID3 "Fiducial" Fiducial10-20 75,75 r180 bottom (schematic designator FID2)
H1 "1903C" KEYSTONE_1903C 1474.9,3600.1 r180 bottom locked (schematic designator H4)
H2 "1903C" KEYSTONE_1903C 4509.9,3025.1 r180 bottom locked (schematic designator H1)
H3 "1903C" KEYSTONE_1903C 5824.9,375.1 r180 bottom locked (schematic designator H2)
H4 "1903C" KEYSTONE_1903C 200,300 r180 bottom locked (schematic designator H3)
H5 "4826" KEYSTONE_4826 1474.9,3600.1 r0 top locked (schematic designator H8)
H6 "4826" KEYSTONE_4826 4509.9,3025.1 r0 top locked (schematic designator H5)
H7 "4826" KEYSTONE_4826 5824.9,375.1 r0 top locked (schematic designator H6)
H8 "4826" KEYSTONE_4826 200,300 r0 top locked (schematic designator H7)
H27 "MPMS 003 0005 PH" BuildingFastener_MPMS_003_0005_PH 6112.81,2477.36 r180 bottom
H28 "MPMS 003 0005 PH" BuildingFastener_MPMS_003_0005_PH 1812.39,1522.64 r180 bottom
H29 "MPMS 003 0005 PH" BuildingFastener_MPMS_003_0005_PH 1812.39,3272.64 r180 bottom
H30 "MPMS 003 0005 PH" BuildingFastener_MPMS_003_0005_PH 3057.69,1522.64 r180 bottom
H31 "MPMS 003 0005 PH" BuildingFastener_MPMS_003_0005_PH 3057.69,3272.64 r180 bottom
H32 "MPMS 003 0005 PH" BuildingFastener_MPMS_003_0005_PH 6112.81,727.36 r180 bottom
HS1 "782653B02000G" HEATSINK_782653B02000G 1913.39,2397.64 r270 top
HS2 "782653B02000G" HEATSINK_782653B02000G 2956.69,2397.64 r90 top
HS3 "782653B02000G" HEATSINK_782653B02000G 6011.81,1602.36 r90 top
J1 "VIN+" CONN_ED120-2DS 531.5,3602.36 r90 top
J2 "VIN-" CONN_ED120-2DS 1043.31,3602.36 r90 top
J3 "CXS70-14-C" Panduit_CXS70-14-C 6614.17,325 r180 top locked
J4 "CXS70-14-C" Panduit_CXS70-14-C 6614.17,3480.32 r180 top
J5 "DF11-14DS-2DSA(05)" Hirose_DF11-14DS-2DSA[05] 3763.9,289.05 r90 top
L1 "75PR8108" 75P 5387,3199 r180 top
L2 "60PR964" 60P 3907,3008 r270 top
Logo1 "Texas Instruments" TI_Stacked_Overlay_Medium 3543.31,797.24 r0 top
LOGO2 "DANGER HIGH VOLTAGE" IEC_HighVoltage_Small 3385.83,3566.93 r0 top
LOGO3 "CAUTION HOT SURFACE" IEC_HotSurface_Small 2444.88,3574.8 r0 top
LOGO4 "CAUTION HOT SURFACE" IEC_HotSurface_Small 2102.36,952.76 r0 top
LOGO5 "DANGER HIGH VOLTAGE" IEC_HighVoltage_Small 1185.04,3299.21 r180 bottom
LOGO6 "CAUTION HOT SURFACE" IEC_HotSurface_Small 5468.5,2763.78 r180 bottom
LOGO7 "CAUTION HOT SURFACE" IEC_HotSurface_Small 4251.97,1078.74 r180 bottom
LOGO8 "DANGER HIGH VOLTAGE" IEC_HighVoltage_Small 133.86,948.82 r270 top
Logo9 "Pb-Free Symbol" Pb-Free_Overlay_Medium 4334.65,1814.96 r180 bottom
Q1 "SPP20N60C3" TO-220AB_100mil 2779.53,2830.71 r270 top
Q2 "SPP20N60C3" TO-220AB_100mil 2779.53,2225.98 r270 top
Q3 "SPP20N60C3" TO-220AB_100mil 2098.43,2633.86 r90 top
Q4 "SPP20N60C3" TO-220AB_100mil 2098.43,2025 r90 top
Q5 "MMBT2222A" SOT-23 2562.99,751.97 r90 bottom
Q6 "CSD19506KCS" TO-220AB_100mil 5830,1160 r270 top
Q7 "CSD19506KCS" TO-220AB_100mil 5830,2265 r270 top
Q8 "MMBT2222A" SOT-23 2503.94,185.04 r90 bottom
R1 "CRCW080548R7FKEA" 0805_HV 790,390 r0 bottom
R2 "ERJ-6ENF4871V" 0805_HV 590,490 r0 bottom
R3 "CRCW12061M00JNEA" 1206 750,2750 r180 bottom
R4 "CRCW08053R01FKEA" 0805_HV 1791.34,2444.88 r90 bottom
R5 "CRCW08053R01FKEA" 0805_HV 2708.66,1543.31 r90 bottom
R6 "CRCW2512100KFKEG" 2512 6005,1975 r90 bottom
R7 "WSC45271K000FEA" 4527_450 6300,1625 r180 bottom
R8 "WSC45271K000FEA" 4527_450 6300,1175 r180 bottom
R9 "ERJ-6ENF49R9V" 0805_HV 5800,100 r0 bottom
R10 "ERJ-6ENF1002V" 0805_HV 2660,1675 r0 bottom
R11 "ERJ-6ENF1002V" 0805_HV 1929.13,2490.16 r0 bottom
R12 "CRCW12061M00JNEA" 1206 925,2625 r90 bottom
R13 "CRCW08053R01FKEA" 0805_HV 2177.17,1700.79 r90 bottom
R14 "CRCW12061M00JNEA" 1206 925,2401.57 r90 bottom
R15 "CRCW08053R01FKEA" 0805_HV 1803.15,1929.13 r90 bottom
R16 "ERJ-6ENF1002V" 0805_HV 1998.03,2125.98 r90 bottom
R17 "ERJ-6ENF1002V" 0805_HV 2007.87,2736.22 r90 bottom
R18 "ERJ-6RQF2R2V" 0805_HV 1462.99,889.76 r180 bottom
R19 "ERJ-6RQF2R2V" 0805_HV 2673.62,938.98 r0 bottom
R20 "ERJ-6ENF7151V" 0805_HV 2712.99,761.81 r270 bottom
R21 "CRCW08056R19FKEA" 0805_HV 4590,680 r180 bottom
R22 "CRCW08056R19FKEA" 0805_HV 5045.67,761.81 r0 bottom
R23 "CRCW08055R11FKEA" 0805_HV 1620.47,791.34 r180 bottom
R24 "ERJ-6ENF1002V" 0805_HV 5880,2410 r0 bottom
R25 "ERJ-6ENF1002V" 0805_HV 5825,825 r90 bottom
R26 "ERJ-6ENF7151V" 0805_HV 2653.94,190.94 r270 bottom
R27 "ERJ-6ENF7151V" 0805_HV 3287.4,216.54 r180 bottom
R28 "ERJ-6ENF5111V" 0805_HV 3090.55,212.6 r0 bottom
R29 "CRCW08055R11FKEA" 0805_HV 5193.31,624.02 r0 bottom
R30 "ERJ-6ENF7151V" 0805_HV 3287.4,98.43 r180 bottom
R31 "ERJ-6ENF5111V" 0805_HV 3090.55,98.43 r0 bottom
R32 "ERJ-6ENF7151V" 0805_HV 3287.4,452.76 r180 bottom
R33 "ERJ-6ENF5111V" 0805_HV 3090.55,452.76 r0 bottom
R34 "ERJ-6ENF7151V" 0805_HV 3287.4,334.65 r180 bottom
R35 "ERJ-6ENF5111V" 0805_HV 3090.55,334.65 r0 bottom
T1 "PE-63587" Pulse_PE6358X 688.98,960.63 r270 top
T2 "75PR8107" VITEC_75PR8107 4515.75,1763.78 r0 top
TP1 "VBULK" Keystone5000 150,1325 r0 top
TP2 "LOOP-" Keystone5002 5600,100 r0 top
TP3 "LOOP+" Keystone5002 6000,100 r0 top
TP4 "VOUT+" Keystone5000 7025,1725 r0 top
TP5 "VOUT-" Keystone5001 7025,1975 r0 top
TP6 "PWRGND" Keystone5001 145,1570 r0 top
TP7 "SYNC" Keystone5002 4900,100 r0 top
TP8 "VBIAS2" Keystone5000 1307.09,704.72 r0 top
TP9 "PWRGND" Keystone5001 1413.39,586.61 r0 top
TP10 "VBIAS" Keystone5000 5300,100 r0 top
TP11 "PWRGND" Keystone5001 5100,100 r0 top
U1 "UCC27714D" D0014A_N 1738.58,1116.14 r90 bottom
U2 "UCC27714D" D0014A_N 2368.5,1116.14 r90 bottom
U3 "UCC27524AD" D0008A_N 4790,610 r90 bottom
U4 "ISO7240MDW" DW0016A_N 2152,497 r90 bottom
ZZ1 "See assembly document for heatsink assembly instructions." AssemblyNote 20.28,6930.68 r0 top
ZZ2 "These assemblies are ESD sensitive, ESD precautions shall be observed." AssemblyNote 20.28,6821.79 r0 top
ZZ3 "These assemblies must be clean and free from flux and all contaminants. Use of no clean flux is not acceptable." AssemblyNote 20.28,6733.23 r0 top
ZZ4 "These assemblies must comply with workmanship standards IPC-A-610 Class 2., unless otherwise specified." AssemblyNote 20.28,6644.68 r0 top

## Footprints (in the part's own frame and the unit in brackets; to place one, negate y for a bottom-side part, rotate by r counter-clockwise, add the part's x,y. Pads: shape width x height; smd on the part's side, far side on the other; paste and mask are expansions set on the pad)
60P [mm] "VITEC"
  rect 1.3x1.3 hole 0.8: 1(-7.62,7.62)
  round 1.3 hole 0.8: 2(-7.62,2.54) 3(-7.62,-2.54) 4(-7.62,-7.62) 5(7.62,-7.62) 6(7.62,-2.54) 7(7.62,2.54) 8(7.62,7.62)
  silkscreen extent -10.94,-10.9 10.05,10.9
75P [mm] "VITEC"
  rect 1.5x1.5 hole 1: 1(-9.85,11.43)
  round 1.5 hole 1: 6(-9.85,-11.43) 7(15.55,-11.43) 12(15.55,11.43)
  round 4.45 hole 3.85: 13(-6.66,0) 14(-15.55,0)
  silkscreen extent -13.04,-14.3 17.75,14.3
440L_930x1250 [mm] "Vishay"
  round 1.6 hole 1.092: 1(-4.75,2) 2(4.75,-2)
  silkscreen extent -4.65,-2.8 4.65,2.8
0805_HV [mil] "0805 with 30mil clearance between pads"
  rect 50x63 smd: 1(-40,0) 2(40,0)
  silkscreen extent -74,-40 74,40
1206 [mm] "1206 from SM-752 data"
  rect 1.3x1.85 smd: 1(-1.45,0) 2(1.45,0)
  silkscreen extent -2.4,-1.21 2.4,1.21
2220 [mm] "Chip Capacitor, Body 5.7x5.0mm, IPC Medium Density"
  rect 1.6x5.3 smd: 1(-2.6,0) 2(2.6,0)
  silkscreen extent -3.69,-2.94 3.69,2.94
2512 [mm] "Chip Resistor, Body 6.3x3.2mm, IPC Medium Density"
  rect 1.3x3.4 smd: 1(-2.95,0) 2(2.95,0)
  silkscreen extent -1.9,-1.6 1.9,1.6
4527_450 [mil] "Vishay recommended land pattern"
  rect 155x230 smd: 1(-180,0) 2(180,0)
  silkscreen extent -275,-150 275,150
AssemblyNote [mil] "Assembly Note"
BuildingFastener_MPMS_003_0005_PH [mil] "MACHINE SCREW PAN PHILLIPS M3"
  round 1 on Mech4: 0(0,0)
CAPRR2250W80L2550T850H1750 [mm] "PANASONIC"
  round 1.55 hole 1.05: 1(-11.25,0) 2(11.25,0)
  silkscreen extent -12.75,-4.25 12.75,4.25
CONN_ED120-2DS [mm] "ONSHORE"
  rect 1.75x1.75 hole 1.25: 1(0,-2.54)
  round 1.75 hole 1.25: 2(0,2.54)
  silkscreen extent -5,-5.6 4,5.12
D0008A_N [mm] "SOIC, 8-Leads, Body 4.9x3.9mm, Pitch 1.27mm, IPC Medium Density"
  oval 2.2x0.6 smd: 1(-2.4,1.905) 2(-2.4,0.635) 3(-2.4,-0.635) 4(-2.4,-1.905) 5(2.4,-1.905) 6(2.4,-0.635) 7(2.4,0.635) 8(2.4,1.905)
  silkscreen extent -0.9,-2.5 0.9,2.5
D0014A_N [mm] "SOIC, 14-Leads, Body 8.7x3.9mm, Pitch 1.27mm, IPC Medium Density"
  oval 2.2x0.6 smd: 1(-2.4,3.81) 2(-2.4,2.54) 3(-2.4,1.27) 4(-2.4,0) 5(-2.4,-1.27) 6(-2.4,-2.54) 7(-2.4,-3.81) 8(2.4,-3.81) 9(2.4,-2.54) 10(2.4,-1.27) 11(2.4,0) 12(2.4,1.27) 13(2.4,2.54) 14(2.4,3.81)
  silkscreen extent -0.9,-4.4 0.9,4.4
DW0016A_N [mm] "SOIC, 16-Leads, Body 10.3x7.5mm, Pitch 1.27mm, IPC Medium Density"
  oval 2.3x0.6 smd: 1(-4.55,4.445) 2(-4.55,3.175) 3(-4.55,1.905) 4(-4.55,0.635) 5(-4.55,-0.635) 6(-4.55,-1.905) 7(-4.55,-3.175) 8(-4.55,-4.445) 9(4.55,-4.445) 10(4.55,-3.175) 11(4.55,-1.905) 12(4.55,-0.635) 13(4.55,0.635) 14(4.55,1.905) 15(4.55,3.175) 16(4.55,4.445)
  silkscreen extent -3,-5.25 3,5.25
Fiducial10-20 [mm]
  round 1 smd mask+0.5: 1(0,0)
  Top Layer keep-out circle w1.178: c0,0 r0.5
HEATSINK_782653B02000G [mil] "Aavid"
  round 220 hole 125: 1(-875,-101) 2(875,-101)
  silkscreen extent -1000,-280 1000,55
Hirose_DF11-14DS-2DSA[05] [mm] "Hirose"
  rect 1.35x1.35 hole 0.85: 1(-1,6)
  round 1.35 hole 0.85: 2(1,6) 3(-1,4) 4(1,4) 5(-1,2) 6(1,2) 7(-1,0) 8(1,0) 9(-1,-2) 10(1,-2) 11(-1,-4) 12(1,-4) 13(-1,-6) 14(1,-6)
  silkscreen extent -3.33,-7.99 2.5,8.01
IEC_HighVoltage_Small [mil]
  silkscreen extent -107,-88 107,97
IEC_HotSurface_Small [mil]
  silkscreen extent -107,-93 107,92
Keystone5000 [mil] "For Keystone 500x miniature loop terminals"
  round 80 hole 40: 1(0,0)
  silkscreen extent -58,-58 58,58
Keystone5001 [mil] "For Keystone 500x miniature loop terminals"
  round 80 hole 40: 1(0,0)
  silkscreen extent -58,-58 58,58
Keystone5002 [mil] "For Keystone 500x miniature loop terminals"
  round 80 hole 40: 1(0,0)
  silkscreen extent -58,-58 58,58
KEYSTONE_1903C [mil] "HEX NYLON STANDOFF 6-32, F-F 0.5\""
  round 1 on Mech4: 0(0,0)
KEYSTONE_4826 [mil] "HEX STANDOFF 6-32 NYLON 1750 mil"
  round 1 on Mech3: 0(0,0)
  round 152 hole 152 unplated: MH(0,0)
  silkscreen extent -151,-151 151,151
KY_1000x3000 [mm] "NIPPON CHEMICON"
  rect 1.5x1.5 hole 0.85: 1(-2.5,0)
  round 1.5 hole 0.85: 2(2.5,0)
  silkscreen extent -5.3,-5.31 5.31,5.31
Littelfuse_0100-0020_54_56 [mm] "Littelfuse"
  round 1.8 hole 1.3: 1(-2.3,0) 2(2.3,0)
  silkscreen extent -2.25,-2.97 2.25,2.97
M_500x1100 [mm] "PANASONIC"
  rect 1.4x1.4 hole 0.75: 1(-1,0)
  round 1.4 hole 0.75: 2(1,0)
  silkscreen extent -2.82,-2.81 2.82,2.82
Panduit_CXS70-14-C [mil] "Panduit"
  rect 770x500 hole 254 copper offset -74.8,0 paste-250: 1(0,0)
  silkscreen extent -960,-230 -480,230
Pb-Free_Overlay_Medium [mil]
  silkscreen extent -95,-95 95,95
Pulse_PE6358X [mil] "Pulse"
  rect 100x100 hole 76 paste+0: 1(-350,250)
  round 100 hole 76 paste+0: 2(-350,-250) 6(-150,250) 7(-150,-250)
  round 60 hole 40 paste+0: 3(350,250) 4(350,0) 5(350,-250)
  silkscreen extent -450,-350 450,350
SMB [mil] "Molded Diode, 2-Leads, Body 5.4x3.6mm, IPC Medium Density, based on OnSemi component dimensions"
  rect 85x107.99 smd: 1(-87.01,0) 2(87.01,0)
  silkscreen extent -155,-82 125,82
SMC [mil] "Molded Diode, 2-Leads, Body 6.9x5.8mm, IPC Medium Density, based on OnSemi component dimensions and land patterns"
  rect 110x150 smd: 1(-140.49,0) 2(140.49,0)
  silkscreen extent -221,-124 189,124
SOD-123 [mm] "On Semi recommended land pattern"
  rect 0.915x1.22 smd: 1(-1.637,0) 2(1.637,0)
  silkscreen extent -2.74,-1.17 2.03,1.17
SOT-23 [mm] "SOT23, 3-Leads, Body 2.9x1.3mm, Pitch 0.95mm, Lead Span 2.5mm, IPC Medium Density"
  rrect50% 1x0.6 smd: 1(-1.2,0.95) 2(-1.2,-0.95) 3(1.2,0)
  silkscreen extent -1.62,-1.5 0.7,1.5
TI_Stacked_Overlay_Medium [mil]
TO-220AB_100mil [mm] "High Voltage staggered pins"
  rect 1.8x1.8 hole 1.3: 1(0,0)
  round 1.8 hole 1.3: 2(2.54,-2.54) 3(5.08,0)
  silkscreen extent -2.29,-2.41 7.36,2.43
TS-HC_3500x3500 [mm] "Panasonic"
  rect 2.7x2.7 hole 2.1: 1(-5,0)
  round 2.7 hole 2.1: 2(5,0)
  silkscreen extent -18,-18 18,18
VITEC_75PR8107 [mm] "VITEC"
  rect 1.7x1.7 hole 1.1: 1(-21.275,15)
  round 1.7 hole 1.1: 2(-21.275,10) 3(-21.275,5) 4(-21.275,-5) 5(-21.275,-10) 6(-21.275,-15)
  round 5.7 hole 5.1: 7(21.275,-15) 9(21.275,-5) 10(21.275,5) 12(21.275,15)
  silkscreen extent -26.27,-19.31 25.01,19.31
